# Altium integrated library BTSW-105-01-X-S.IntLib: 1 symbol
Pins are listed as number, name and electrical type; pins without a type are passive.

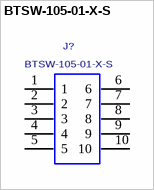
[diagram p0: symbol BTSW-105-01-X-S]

## BTSW-105-01-X-S
designator J?
.025 [.64] SQ. SINGLE ROW, DOUBLE -RA POST ASM.; MANUFACTURER: SAMTEC
footprint BTSW-105-01-X-S
pins: 1, 2, 3, 4, 5, 6, 7, 8, 9, 10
